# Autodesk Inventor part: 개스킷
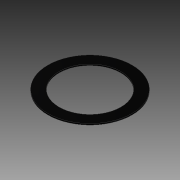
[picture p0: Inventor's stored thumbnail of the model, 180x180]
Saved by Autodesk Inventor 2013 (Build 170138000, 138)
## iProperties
Created: 2022-05
Part Number: 개스킷
Material: 황동, 연질 노란색
Document SubType Name: Modeling
Designer: mdu-01
Density: 1 g/cm^3
Author: mdu-01
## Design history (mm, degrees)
sketch "스케치1"
  geometry: C1 r 23.5 at (0, 0); C2 r 32 at (0, 0); 1 further point
  constraints: 2 centre point, 2 coincident
  dimensions: "d0" = 47 diameter of C1; "d1" = 64 diameter of C2
extrude "돌출1" new body sketch "스케치1" stored distance "d2" = 1; taper "d3" = 0 deg
node "솔리드1"
